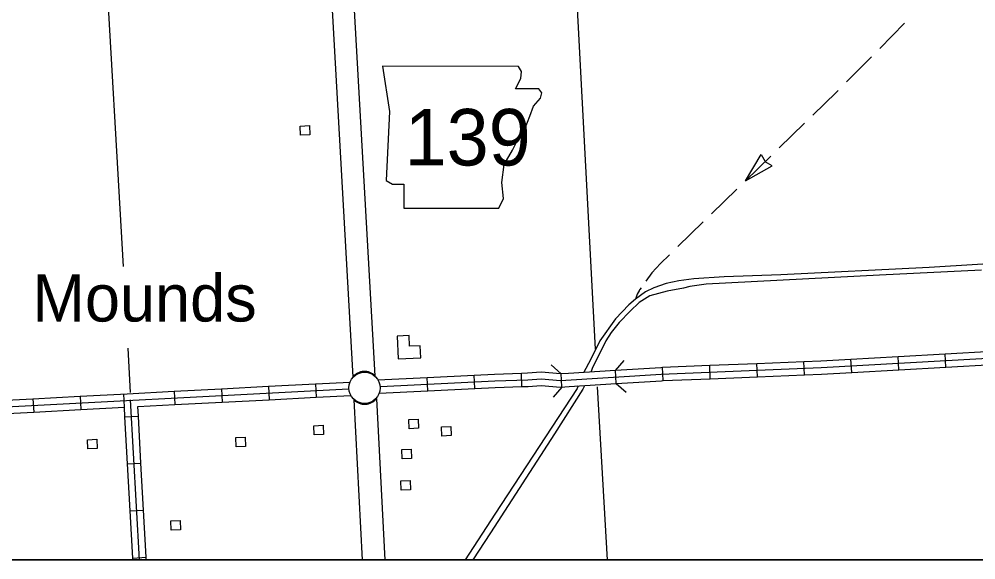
# Model space of a CAD drawing. Extents: x -0.3 to 2.65, y 0 to 1.9.
# Drawn here: x 0.7514 to 0.8796, y 0.1443 to 0.2167 of the extents above; entities that cross this region are included whole.
import ezdxf

# ---------------------------------------------------------------- set-up
doc = ezdxf.new("R2010")
doc.units = 0
for name, color, linetype in [('DSN_DRFT_DNC', 7, 'Continuous'), ('Level 12', 7, 'Continuous'), ('Level 14', 7, 'Continuous'), ('Level 15', 7, 'Continuous'), ('Level 19', 7, 'Continuous'), ('Level 20', 7, 'Continuous'), ('Level 21', 7, 'Continuous'), ('Level 22', 7, 'Continuous'), ('Level 24', 7, 'Continuous'), ('Level 29', 7, 'Continuous'), ('Level 31', 7, 'Continuous'), ('Level 6', 7, 'Continuous')]:
    doc.layers.add(name, color=color, linetype=linetype)

msp = doc.modelspace()

# ---------------------------------------------------------------- linework, layer by layer
at = {"layer": 'DSN_DRFT_DNC'}
msp.add_lwpolyline([(0.38477044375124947, 0.541666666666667), (1.0318962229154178, 0.541666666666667), (1.0318962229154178, 0.14429633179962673), (0.38477044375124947, 0.14429633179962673)], close=True, dxfattribs=at)
at = {"layer": 'Level 12'}
for p, q in [((0.8487578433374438, 0.19506926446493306), (0.8508580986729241, 0.19859838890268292)), ((0.8508580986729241, 0.19859838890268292), (0.8513922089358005, 0.19764437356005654)), ((0.8523412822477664, 0.19707544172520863), (0.8514022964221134, 0.19763425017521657)), ((0.8487578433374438, 0.19506926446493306), (0.8523412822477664, 0.19707544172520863))]:
    msp.add_line(p, q, dxfattribs=at)
for points in [[(0.8700902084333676, 0.21617640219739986), (0.8667566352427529, 0.21280866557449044)], [(0.8656454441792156, 0.21168608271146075), (0.8623118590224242, 0.20831834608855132)], [(0.861200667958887, 0.20719576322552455), (0.8609649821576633, 0.2069576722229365), (0.8578102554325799, 0.20388532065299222)], [(0.856678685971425, 0.20278329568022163), (0.8532839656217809, 0.19947720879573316)], [(0.8521523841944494, 0.19837518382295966), (0.8487576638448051, 0.1950690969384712)], [(0.8476260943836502, 0.19396707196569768), (0.8442313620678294, 0.1906609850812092)], [(0.8430997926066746, 0.18955896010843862), (0.8397050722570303, 0.18625287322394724)], [(0.8385734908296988, 0.18515084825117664), (0.8373838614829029, 0.18399227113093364), (0.8362391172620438, 0.18275476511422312), (0.8354232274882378, 0.1816266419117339)], [(0.83451523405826, 0.18033553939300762), (0.8342657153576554, 0.17988478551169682), (0.8340188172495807, 0.1792137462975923)]]:
    msp.add_lwpolyline(points, dxfattribs=at)
at = {"layer": 'Level 14'}
for points in [[(0.8928005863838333, 0.1846438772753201), (0.8733845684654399, 0.18343789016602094), (0.8535032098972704, 0.18247645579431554), (0.845924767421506, 0.1821917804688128), (0.8418535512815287, 0.18192341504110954), (0.8398180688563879, 0.18164510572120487), (0.838156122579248, 0.18131054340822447), (0.8365038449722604, 0.18074818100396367), (0.8353550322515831, 0.1801711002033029), (0.8340188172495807, 0.1792137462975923), (0.8331415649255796, 0.1784439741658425), (0.8313420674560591, 0.1765542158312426), (0.8292511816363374, 0.1736312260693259), (0.8280393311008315, 0.17115378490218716), (0.8270765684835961, 0.16935315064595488)], [(0.8803784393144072, 0.18310931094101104), (0.8667100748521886, 0.18244681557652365), (0.8434885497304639, 0.1811998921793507), (0.8412972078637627, 0.1809270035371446), (0.8404453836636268, 0.18068677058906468), (0.8382959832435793, 0.18027153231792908), (0.83595105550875, 0.17966785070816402), (0.8345296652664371, 0.17874293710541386), (0.8332966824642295, 0.1776098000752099), (0.8318414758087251, 0.17607090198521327), (0.8307849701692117, 0.174729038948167), (0.8300534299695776, 0.17362913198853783), (0.8282470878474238, 0.1699254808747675), (0.828076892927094, 0.16950471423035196)], [(0.8347738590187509, 0.18072875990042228), (0.8345993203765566, 0.1804874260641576), (0.8342657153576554, 0.17988478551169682), (0.8340188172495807, 0.1792137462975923)], [(0.8347738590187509, 0.18072875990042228), (0.8345993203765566, 0.1804874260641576), (0.8342657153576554, 0.17988478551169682), (0.8340188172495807, 0.1792137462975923)], [(0.8263532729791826, 0.16758723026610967), (0.8262067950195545, 0.1672208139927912), (0.815163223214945, 0.15040696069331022), (0.8112035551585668, 0.14427389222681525)], [(0.8272164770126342, 0.16761639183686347), (0.8269762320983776, 0.1671452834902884), (0.8231835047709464, 0.16115961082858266), (0.8146231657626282, 0.1478979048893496), (0.8122375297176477, 0.14427389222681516)]]:
    msp.add_lwpolyline(points, dxfattribs=at)
at = {"layer": 'Level 15'}
for p, q in [((0.8756176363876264, 0.17010997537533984), (0.8755161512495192, 0.17190202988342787)), ((0.850365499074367, 0.16881235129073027), (0.8502916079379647, 0.1706057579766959)), ((0.8566782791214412, 0.16907242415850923), (0.8566043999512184, 0.17086583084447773)), ((0.8630015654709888, 0.16939551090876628), (0.8629000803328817, 0.17118756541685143)), ((0.8693095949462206, 0.16975273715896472), (0.8692081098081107, 0.17154479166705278)), ((0.8188214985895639, 0.16749856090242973), (0.8187601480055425, 0.16929243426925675)), ((0.8241745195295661, 0.16744492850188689), (0.8240619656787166, 0.16923632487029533)), ((0.8314529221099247, 0.16790222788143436), (0.8313403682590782, 0.16969362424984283)), ((0.8377399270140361, 0.16829220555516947), (0.8376660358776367, 0.17008561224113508)), ((0.8440527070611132, 0.16855227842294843), (0.8439788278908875, 0.17034568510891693)), ((0.806210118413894, 0.1669410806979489), (0.8061236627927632, 0.16873392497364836)), ((0.8125209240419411, 0.16724540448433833), (0.8124344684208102, 0.1690382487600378)), ((0.7722273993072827, 0.16686546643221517), (0.7723216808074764, 0.16507301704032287)), ((0.7785368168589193, 0.16719736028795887), (0.7786310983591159, 0.16540491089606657)), ((0.7848462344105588, 0.16752926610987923), (0.7849405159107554, 0.16573681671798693)), ((0.7911556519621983, 0.16786115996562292), (0.791249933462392, 0.16606871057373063)), ((0.7532991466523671, 0.1658697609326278), (0.7533934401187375, 0.16407731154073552)), ((0.7596085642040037, 0.16620165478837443), (0.759702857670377, 0.16440920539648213)), ((0.7654411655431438, 0.16650847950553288), (0.7655354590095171, 0.16471603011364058)), ((0.7675667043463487, 0.14427389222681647), (0.7663852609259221, 0.16569818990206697)), ((0.7656273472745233, 0.1634436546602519), (0.7674195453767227, 0.16354249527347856)), ((0.7659752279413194, 0.15713509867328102), (0.7677674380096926, 0.15723393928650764)), ((0.7663231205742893, 0.15082654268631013), (0.7681153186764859, 0.15092538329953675)), ((0.7666710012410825, 0.1445179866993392), (0.7684632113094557, 0.14461682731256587)), ((0.7666844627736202, 0.1442738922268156), (0.7666710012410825, 0.1445179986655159)), ((0.7684821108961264, 0.14427389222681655), (0.768463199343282, 0.14461682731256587))]:
    msp.add_line(p, q, dxfattribs=at)
for points in [[(0.7998568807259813, 0.16751664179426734), (0.8151722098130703, 0.1682551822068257), (0.8196075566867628, 0.16840685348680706), (0.8213857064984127, 0.16854215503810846), (0.8239933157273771, 0.16831619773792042), (0.8374623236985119, 0.1691624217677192), (0.8589034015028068, 0.1700457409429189), (0.8916292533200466, 0.17189903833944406), (0.9040168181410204, 0.1725553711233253), (0.9119873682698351, 0.1731929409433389), (0.915659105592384, 0.1735645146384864), (0.9197867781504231, 0.17363108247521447), (0.9292031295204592, 0.174053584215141), (0.9333351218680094, 0.17430050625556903), (0.9529937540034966, 0.17619840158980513)], [(0.8692081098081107, 0.17154480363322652), (0.8755161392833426, 0.17190202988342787)], [(0.8755161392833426, 0.17190202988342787), (0.8818241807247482, 0.1722592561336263)], [(0.8439788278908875, 0.17034568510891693), (0.8502916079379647, 0.1706057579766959)], [(0.8502916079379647, 0.1706057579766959), (0.8566043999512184, 0.17086581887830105)], [(0.8566043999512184, 0.17086581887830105), (0.8588587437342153, 0.17095870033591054), (0.8629000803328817, 0.17118756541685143)], [(0.8629000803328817, 0.17118756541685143), (0.8692081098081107, 0.17154480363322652)], [(0.8124344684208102, 0.1690382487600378), (0.8151345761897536, 0.1691684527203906), (0.8187601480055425, 0.16929243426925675)], [(0.8187601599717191, 0.16929243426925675), (0.8195572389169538, 0.1693196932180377), (0.8213905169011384, 0.16945918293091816), (0.8240041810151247, 0.1692327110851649), (0.8250346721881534, 0.1692974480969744)], [(0.8250346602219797, 0.1692974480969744), (0.8313403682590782, 0.16969362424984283)], [(0.8313403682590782, 0.16969362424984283), (0.8374148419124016, 0.17007526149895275), (0.83766602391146, 0.17008561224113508)], [(0.8376660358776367, 0.17008561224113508), (0.8439788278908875, 0.17034568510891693)], [(0.8566782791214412, 0.16907241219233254), (0.8589464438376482, 0.16916586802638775), (0.8630015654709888, 0.16939551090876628)], [(0.8630015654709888, 0.16939551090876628), (0.8693095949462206, 0.1697527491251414)], [(0.8693095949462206, 0.1697527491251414), (0.8756176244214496, 0.17010997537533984)], [(0.8756176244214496, 0.17010997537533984), (0.8819256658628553, 0.1704672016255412)], [(0.7911556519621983, 0.16786115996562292), (0.7957884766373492, 0.16810486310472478)], [(0.7995196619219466, 0.1684154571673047), (0.8061236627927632, 0.16873392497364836)], [(0.8061236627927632, 0.16873392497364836), (0.8124344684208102, 0.1690382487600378)], [(0.8314529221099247, 0.16790222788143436), (0.8375080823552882, 0.16828265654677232), (0.8377399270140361, 0.16829220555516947)], [(0.8377399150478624, 0.16829220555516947), (0.8440527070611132, 0.16855227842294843)], [(0.8440527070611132, 0.16855227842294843), (0.8503654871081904, 0.16881235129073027)], [(0.8503654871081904, 0.16881235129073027), (0.8566782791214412, 0.16907241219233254)], [(0.6735932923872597, 0.1442738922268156), (0.6734143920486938, 0.14690668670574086), (0.6734838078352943, 0.14724591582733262), (0.6956273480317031, 0.15950904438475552), (0.6984037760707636, 0.16094770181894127), (0.6998310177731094, 0.16145249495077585), (0.7011911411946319, 0.16184634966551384), (0.7027928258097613, 0.16219037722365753), (0.7044115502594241, 0.16241501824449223), (0.7281161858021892, 0.16356227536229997), (0.7428530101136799, 0.16443812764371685), (0.7955926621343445, 0.16721244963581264)], [(0.7659179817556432, 0.16653356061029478), (0.7722273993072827, 0.16686545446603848)], [(0.7722273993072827, 0.16686545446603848), (0.7785368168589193, 0.16719736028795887)], [(0.7785368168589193, 0.16719736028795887), (0.7848462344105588, 0.16752925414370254)], [(0.7848462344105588, 0.16752925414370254), (0.7911556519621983, 0.16786115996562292)], [(0.7997064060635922, 0.16662745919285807), (0.806210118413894, 0.1669410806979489)], [(0.806210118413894, 0.1669410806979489), (0.8125209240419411, 0.16724540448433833)], [(0.8125209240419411, 0.16724540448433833), (0.8152084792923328, 0.16737501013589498), (0.8188214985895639, 0.16749856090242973)], [(0.8188214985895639, 0.16749856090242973), (0.8196560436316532, 0.167527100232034), (0.8213810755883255, 0.16765835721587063), (0.8239828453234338, 0.16743290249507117), (0.8251472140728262, 0.16750605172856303)], [(0.8251472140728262, 0.16750605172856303), (0.8314529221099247, 0.16790222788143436)], [(0.7469897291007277, 0.16553785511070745), (0.7532991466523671, 0.16586974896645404)], [(0.7532991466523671, 0.16586974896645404), (0.7596085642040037, 0.16620165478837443)], [(0.7596085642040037, 0.16620165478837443), (0.7659179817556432, 0.16653356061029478)], [(0.7723216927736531, 0.16507300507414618), (0.7786311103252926, 0.16540491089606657)], [(0.7786310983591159, 0.16540491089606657), (0.7849405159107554, 0.16573680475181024)], [(0.7849405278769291, 0.16573680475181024), (0.7912499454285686, 0.16606871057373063)], [(0.7912499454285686, 0.16606871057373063), (0.7958984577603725, 0.16631323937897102)], [(0.7533934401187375, 0.16407729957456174), (0.759702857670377, 0.16440920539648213)], [(0.759702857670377, 0.16440920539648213), (0.7655571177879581, 0.16471716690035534)], [(0.7656273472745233, 0.1634436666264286), (0.7655571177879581, 0.16471716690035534)], [(0.7673495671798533, 0.16481146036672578), (0.7723216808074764, 0.16507300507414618)], [(0.7674195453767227, 0.16354249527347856), (0.7673495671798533, 0.16481146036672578)], [(0.7470840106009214, 0.16374540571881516), (0.7533934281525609, 0.16407729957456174)], [(0.7659752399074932, 0.1571351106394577), (0.7656273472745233, 0.1634436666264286)], [(0.7677674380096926, 0.15723393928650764), (0.7674195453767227, 0.16354249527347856)], [(0.7663231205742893, 0.1508265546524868), (0.7659752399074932, 0.1571351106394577)], [(0.7681153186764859, 0.15092538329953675), (0.7677674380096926, 0.15723393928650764)], [(0.7666710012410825, 0.1445179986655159), (0.7663231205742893, 0.1508265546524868)], [(0.768463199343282, 0.14461682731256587), (0.7681153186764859, 0.15092538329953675)]]:
    msp.add_lwpolyline(points, dxfattribs=at)
at = {"layer": 'Level 19'}
for points in [[(0.7891411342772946, 0.20117175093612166), (0.7890884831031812, 0.20241613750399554), (0.7903365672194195, 0.2024689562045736), (0.7903892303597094, 0.2012245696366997)], [(0.803720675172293, 0.16185137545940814), (0.8036680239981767, 0.16309576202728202), (0.8049161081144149, 0.1631485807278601), (0.8049687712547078, 0.1619041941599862)], [(0.7909912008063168, 0.161012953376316), (0.7909385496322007, 0.16225733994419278), (0.7921866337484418, 0.16231015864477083), (0.7922392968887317, 0.16106577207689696)], [(0.808095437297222, 0.16086842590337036), (0.8080427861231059, 0.16211281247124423), (0.8092908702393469, 0.1621656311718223), (0.8093435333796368, 0.1609212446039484)], [(0.7606694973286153, 0.15913215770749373), (0.7606168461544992, 0.16037654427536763), (0.7618649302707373, 0.1604293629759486), (0.7619175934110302, 0.1591849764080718)], [(0.7805338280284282, 0.15940967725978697), (0.780481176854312, 0.16065406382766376), (0.7817292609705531, 0.16070688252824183), (0.781781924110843, 0.15946249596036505)], [(0.8027603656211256, 0.15781611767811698), (0.8027077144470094, 0.15906050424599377), (0.8039557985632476, 0.15911332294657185), (0.8040084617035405, 0.15786893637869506)], [(0.802653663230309, 0.15362567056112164), (0.8026010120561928, 0.15487005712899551), (0.8038490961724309, 0.1549228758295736), (0.8039017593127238, 0.15367848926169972)], [(0.7718237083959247, 0.14825203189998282), (0.7717710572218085, 0.1494964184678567), (0.7730191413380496, 0.14954923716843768), (0.7730718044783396, 0.1483048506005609)]]:
    msp.add_lwpolyline(points, close=True, dxfattribs=at)
at = {"layer": 'Level 20'}
msp.add_line((0.830295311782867, 0.1442738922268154), (0.8289336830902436, 0.16744691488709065), dxfattribs=at)
for points in [[(0.8286594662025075, 0.17250891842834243), (0.8255765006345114, 0.23086770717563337)], [(0.7628480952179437, 0.2276760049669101), (0.7653639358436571, 0.18359376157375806)], [(0.7659876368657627, 0.17266540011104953), (0.7663288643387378, 0.16668641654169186)]]:
    msp.add_lwpolyline(points, dxfattribs=at)
at = {"layer": 'Level 21'}
for p, q in [((0.7974473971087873, 0.1442738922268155), (0.7963188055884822, 0.16571516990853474)), ((0.7993065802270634, 0.16586546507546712), (0.8004430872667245, 0.14427389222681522))]:
    msp.add_line(p, q, dxfattribs=at)
for points in [[(0.7930805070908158, 0.22358029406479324), (0.7961520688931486, 0.16878299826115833)], [(0.7991394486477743, 0.16894113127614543), (0.7960792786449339, 0.22353494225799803)]]:
    msp.add_lwpolyline(points, dxfattribs=at)
for centre, radius, start, end in [((0.7977177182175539, 0.167502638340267), 0.002022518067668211, 45.33578333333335, 140.72431666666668), ((0.7977449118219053, 0.16713776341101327), 0.002014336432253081, 224.92934862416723, 320.8301395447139)]:
    msp.add_arc(centre, radius, start, end, dxfattribs=at)
at = {"layer": 'Level 22'}
msp.add_lwpolyline([(0.8001381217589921, 0.21041959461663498), (0.8010491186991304, 0.20434630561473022), (0.80064423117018, 0.195135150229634), (0.8014540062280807, 0.19462904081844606), (0.8029723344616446, 0.19462904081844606), (0.8029723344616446, 0.19138996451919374), (0.8157262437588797, 0.19138996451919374), (0.8163335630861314, 0.19270582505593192), (0.8161311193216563, 0.19483148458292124), (0.816434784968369, 0.19726080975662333), (0.8175482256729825, 0.19918400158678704), (0.8182567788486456, 0.20060110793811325), (0.8192689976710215, 0.20211944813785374), (0.819876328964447, 0.20373898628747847), (0.8203824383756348, 0.2050548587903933), (0.8212934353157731, 0.20616829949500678), (0.8214958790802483, 0.20687685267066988), (0.8210909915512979, 0.20738296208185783), (0.8179531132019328, 0.20738296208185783), (0.8186616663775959, 0.20880006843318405), (0.8187628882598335, 0.20971105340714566), (0.8183431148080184, 0.21041066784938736)], close=True, dxfattribs=at)
at = {"layer": 'Level 24'}
msp.add_circle((0.7977319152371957, 0.1673249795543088), 0.002094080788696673, dxfattribs=at)
at = {"layer": 'Level 29'}
for points in [[(0.8313432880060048, 0.16966692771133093), (0.8325304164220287, 0.17101321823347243)], [(0.8227224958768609, 0.17040151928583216), (0.8240687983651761, 0.16921440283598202)], [(0.8241813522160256, 0.1674229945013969), (0.8229942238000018, 0.1660767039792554)], [(0.8328021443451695, 0.16668840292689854), (0.8314558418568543, 0.16787551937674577)]]:
    msp.add_lwpolyline(points, dxfattribs=at)
at = {"layer": 'Level 31'}
msp.add_lwpolyline([(0.8022158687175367, 0.17123420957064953), (0.8052527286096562, 0.1713627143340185), (0.8051849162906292, 0.1729649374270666), (0.803747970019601, 0.17290412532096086), (0.8036872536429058, 0.17433878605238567), (0.8020873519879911, 0.17427108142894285)], close=True, dxfattribs=at)
at = {"layer": 'Level 6'}
msp.add_line((0.3847599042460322, 0.14427389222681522), (1.0318856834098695, 0.14427389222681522), dxfattribs=at)

# ---------------------------------------------------------------- texts
at = {"layer": 'Level 22'}
msp.add_text('139', height=0.007574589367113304, dxfattribs=at).set_placement((0.8030941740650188, 0.19712496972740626))
at = {"layer": 'Level 24'}
msp.add_text('Mounds', height=0.0063181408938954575, dxfattribs=at).set_placement((0.7532188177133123, 0.17621657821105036))

doc.saveas('drawing.dxf')
